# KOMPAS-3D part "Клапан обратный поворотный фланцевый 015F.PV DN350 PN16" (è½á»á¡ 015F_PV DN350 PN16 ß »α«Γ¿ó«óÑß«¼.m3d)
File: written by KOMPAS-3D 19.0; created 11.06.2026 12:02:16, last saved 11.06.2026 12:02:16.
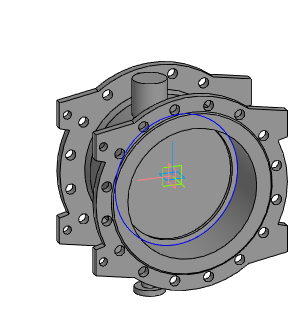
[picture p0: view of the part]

Document properties: Автор: Энергия; Полное имя файла: Z:\3.Личные\kachalov\001_3d для проектировщиков\5.5 Тип 015F.PV Клапан обратный поворотный с двумя эксцентриками\_stp_Клапан 015F.PV DN300-DN1200 с противовесом\Клапан 015F_PV DN350 PN16 с противовесом.m3d

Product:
- Part/product: Клапан обратный поворотный фланцевый 015F.PV DN350 PN16

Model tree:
1. Операция без истории:1
2. Сплайн:1
     Координата Y = 30; Координата Z = 175; Вес = 1; Координата X = 350; Координата Y = 76.0784; Координата Z = 175; Вес = 0.333333; Координата X = 350; Координата Y = 76.0784; Координата Z = -175; Вес = 0.333333; Координата Y = 30; Координата Z = -175; Вес = 1; Координата X = -350; Координата Y = -16.0784; Координата Z = -175; Вес = 0.333333; Координата X = -350; Координата Y = -16.0784; Координата Z = 175; Вес = 0.333333; Порядок = 4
